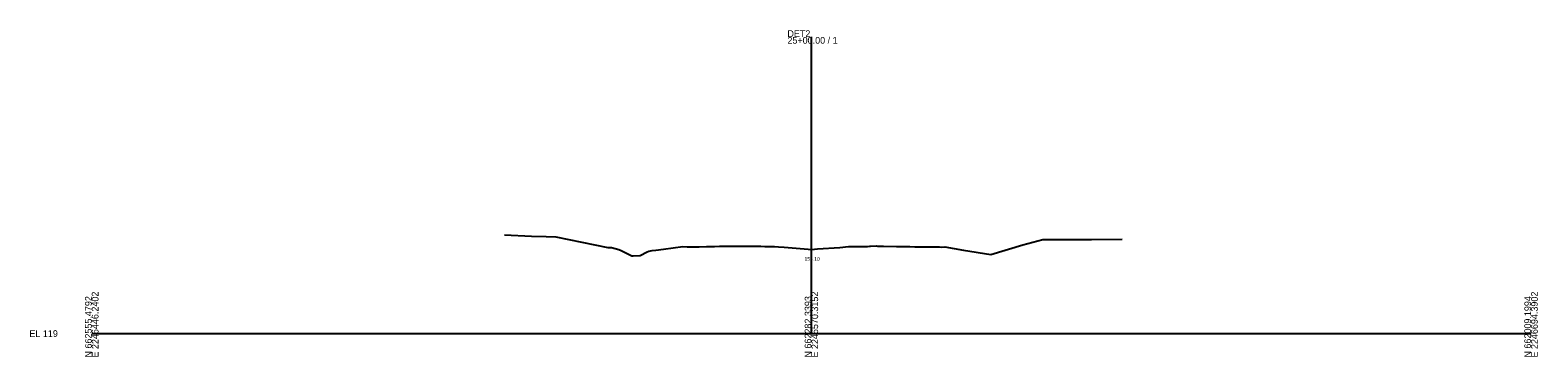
# Model space of a CAD drawing. Extents: x -26 to 603, y -10 to 9526.
# Drawn here: x -26 to 603, y 7990 to 8126 of the extents above; entities that cross this region are included whole.
import ezdxf

# ---------------------------------------------------------------- set-up
doc = ezdxf.new("R2010")
doc.units = 0
for name, color, linetype in [('Default', 7, 'Continuous'), ('Exist Cross Section Cell', 7, 'Continuous'), ('Exist XS Center Line Elevation Label', 7, 'Continuous'), ('Exist XS Ground Line', 7, 'Continuous')]:
    doc.layers.add(name, color=color, linetype=linetype)

msp = doc.modelspace()

# ---------------------------------------------------------------- linework, layer by layer
at = {"layer": 'Exist Cross Section Cell'}
for p, q in [((300, 8000), (300, 8123.58)), ((0, 8000), (300, 8000)), ((300, 8000), (600, 8000))]:
    msp.add_line(p, q, dxfattribs=at)
at = {"layer": 'Exist XS Ground Line'}
for p, q in [((172.09, 8041.19), (183.29, 8040.54)), ((183.29, 8040.54), (189.39, 8040.39)), ((189.39, 8040.39), (193.46, 8040.32)), ((193.46, 8040.32), (215.09, 8035.87)), ((388.17, 8037.03), (396.41, 8039.19)), ((396.41, 8039.19), (408.39, 8039.2)), ((408.39, 8039.2), (416.74, 8039.25)), ((416.74, 8039.25), (429.55, 8039.29)), ((215.09, 8035.87), (216.67, 8035.86)), ((216.67, 8035.86), (219.7, 8035.08)), ((219.7, 8035.08), (220.68, 8034.6)), ((220.68, 8034.6), (225.15, 8032.35)), ((228.61, 8032.53), (231.59, 8034.05)), ((231.59, 8034.05), (232.19, 8034.36)), ((232.19, 8034.36), (233.64, 8034.56)), ((233.64, 8034.56), (235.16, 8034.8)), ((235.16, 8034.8), (238.37, 8035.17)), ((238.37, 8035.17), (246.36, 8036.28)), ((246.36, 8036.28), (248.24, 8036.13)), ((248.24, 8036.13), (248.98, 8036.15)), ((248.98, 8036.15), (252.44, 8036.2)), ((252.44, 8036.2), (253.14, 8036.21)), ((253.14, 8036.21), (256.21, 8036.26)), ((256.21, 8036.26), (258.64, 8036.3)), ((258.64, 8036.3), (259.65, 8036.32)), ((259.65, 8036.32), (261.71, 8036.37)), ((261.71, 8036.37), (262.39, 8036.35)), ((262.39, 8036.35), (264.13, 8036.36)), ((264.13, 8036.36), (267.54, 8036.38)), ((267.54, 8036.38), (269.62, 8036.39)), ((269.62, 8036.39), (271.32, 8036.4)), ((271.32, 8036.4), (273.76, 8036.48)), ((273.76, 8036.48), (274.17, 8036.45)), ((274.17, 8036.45), (275.11, 8036.41)), ((275.11, 8036.41), (278.87, 8036.38)), ((278.87, 8036.38), (280.6, 8036.34)), ((280.6, 8036.34), (283.32, 8036.31)), ((283.32, 8036.31), (284.66, 8036.31)), ((284.66, 8036.31), (286.29, 8036.11)), ((286.29, 8036.11), (288.63, 8036.02)), ((288.63, 8036.02), (298.66, 8035.21)), ((298.66, 8035.21), (300.02, 8035.09)), ((300.02, 8035.09), (302.56, 8035.25)), ((302.56, 8035.25), (311.79, 8035.84)), ((311.79, 8035.84), (315.52, 8036.3)), ((315.52, 8036.3), (317.43, 8036.3)), ((317.43, 8036.3), (319.04, 8036.28)), ((319.04, 8036.28), (320.41, 8036.3)), ((320.41, 8036.3), (323.42, 8036.34)), ((323.42, 8036.34), (324.19, 8036.35)), ((324.19, 8036.35), (324.57, 8036.37)), ((324.57, 8036.37), (326.94, 8036.5)), ((326.94, 8036.5), (327.51, 8036.47)), ((327.51, 8036.47), (328.18, 8036.42)), ((328.18, 8036.42), (330.03, 8036.36)), ((330.03, 8036.36), (335.52, 8036.29)), ((335.52, 8036.29), (337.75, 8036.26)), ((337.75, 8036.26), (338.37, 8036.27)), ((338.37, 8036.27), (339.08, 8036.28)), ((339.08, 8036.28), (339.99, 8036.23)), ((339.99, 8036.23), (341.01, 8036.22)), ((341.01, 8036.22), (343.07, 8036.19)), ((343.07, 8036.19), (346.5, 8036.14)), ((346.5, 8036.14), (347.34, 8036.15)), ((347.34, 8036.15), (349.76, 8036.18)), ((349.76, 8036.18), (350.16, 8036.21)), ((350.16, 8036.21), (351.31, 8036.16)), ((351.31, 8036.16), (351.99, 8036.08)), ((351.99, 8036.08), (353.42, 8036.09)), ((353.42, 8036.09), (354.44, 8036.01)), ((354.44, 8036.01), (355.66, 8036.16)), ((355.66, 8036.16), (363.44, 8034.81)), ((363.44, 8034.81), (374.74, 8032.98)), ((374.74, 8032.98), (388.17, 8037.03)), ((225.15, 8032.35), (225.67, 8032.36)), ((225.67, 8032.36), (228.61, 8032.53))]:
    msp.add_line(p, q, dxfattribs=at)

# ---------------------------------------------------------------- texts
at = {"layer": 'Default'}
msp.add_text('-', height=0.0001, dxfattribs=at).set_placement((0, 8000))
msp.add_text('-', height=0.0001, dxfattribs=at).set_placement((0, 8000))
at = {"layer": 'Exist Cross Section Cell'}
for s, p in [('25+00.00 / 1', (290, 8120.78)), ('DET2', (290, 8123.58)), ('EL 119', (-26, 7998.6))]:
    msp.add_text(s, height=2.8, dxfattribs=at).set_placement(p)
for s, p in [('N 662555.4792', (0, 7990)), ('E 2246446.2402', (2.8, 7990)), ('N 662282.3393', (300, 7990)), ('E 2246570.3152', (302.8, 7990)), ('N 662009.1994', (600, 7990)), ('E 2246694.3902', (602.8, 7990))]:
    msp.add_text(s, height=2.8, rotation=90, dxfattribs=at).set_placement(p)
at = {"layer": 'Exist XS Center Line Elevation Label'}
msp.add_text('154.10', height=1.5, dxfattribs=at).set_placement((297.14, 8030.35))

doc.saveas('drawing.dxf')
